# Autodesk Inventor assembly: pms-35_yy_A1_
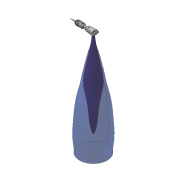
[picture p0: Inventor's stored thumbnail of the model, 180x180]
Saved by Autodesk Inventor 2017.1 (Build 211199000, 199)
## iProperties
Part Number: pms-35_yy_A1_
Material: Generisch
Document SubType Name: Assembly
Designer: Oliver Liedtke
Author: Oliver Liedtke
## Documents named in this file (6)
- J:\Projekte\Kunststoff-Blechteile\Zeichnungen\Bibliothek Inventor\3D Solids\pms\ipt_iam\pms-35_yy_A1_.iam
- J:\Projekte\Kunststoff-Blechteile\Zeichnungen\Bibliothek Inventor\Stecker_Kabel\Lapp\SKINTOP Hygienic-M20x1,5      Art_ Nr_ 531051209.ipt
- J:\Projekte\Kunststoff-Blechteile\Zeichnungen\Pommes-Sensor\Paddle V5\pms-xxx_yy_A1.ipt
- J:\Projekte\Kunststoff-Blechteile\Zeichnungen\Bibliothek Inventor\Stecker_Kabel\mic-Stecker\KSTG-M8.ipt
- J:\Projekte\Kunststoff-Blechteile\Zeichnungen\Bibliothek Inventor\3D Solids\Schallfelder\IPT\detection range 350mm pipe + Blindzone.ipt
- J:\Projekte\Kunststoff-Blechteile\Zeichnungen\Bibliothek Inventor\3D Solids\Schallfelder\IPT\detection range 350 mm plate + Blindzone.ipt
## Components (5 placed, 5 different names)
1. pms-xxx_yy_A1:1 — Passend:1, Passend:2, Passend:3, Passend:4, Passend:5, Winkel:1, Passend:7, Passend:8, Passend:9
2. KSTG-M8:1 — Passend:2, Passend:3, Passend:4
3. SKINTOP Hygienic-M20x1,5      Art_ Nr_ 531051209:1 — Passend:1, Passend:5, Winkel:1
4. detection range 350mm pipe + Blindzone:1 — Passend:6, Passend:9
5. detection range 350 mm plate + Blindzone:1 — Passend:6, Passend:7, Passend:8
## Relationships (10: Mate 9, Angle 1)
- Passend:1 [Mate]: pms-xxx_yy_A1:1 ↔ SKINTOP Hygienic-M20x1,5      Art_ Nr_ 531051209:1
- Passend:2 [Mate]: pms-xxx_yy_A1:1 ↔ KSTG-M8:1
- Passend:3 [Mate]: pms-xxx_yy_A1:1 ↔ KSTG-M8:1
- Passend:4 [Mate]: pms-xxx_yy_A1:1 ↔ KSTG-M8:1
- Passend:5 [Mate]: pms-xxx_yy_A1:1 ↔ SKINTOP Hygienic-M20x1,5      Art_ Nr_ 531051209:1
- Winkel:1 [Angle]: pms-xxx_yy_A1:1 ↔ SKINTOP Hygienic-M20x1,5      Art_ Nr_ 531051209:1
- Passend:6 [Mate]: detection range 350mm pipe + Blindzone:1 ↔ detection range 350 mm plate + Blindzone:1
- Passend:7 [Mate]: pms-xxx_yy_A1:1 ↔ detection range 350 mm plate + Blindzone:1
- Passend:8 [Mate]: pms-xxx_yy_A1:1 ↔ detection range 350 mm plate + Blindzone:1
- Passend:9 [Mate]: pms-xxx_yy_A1:1 ↔ detection range 350mm pipe + Blindzone:1
